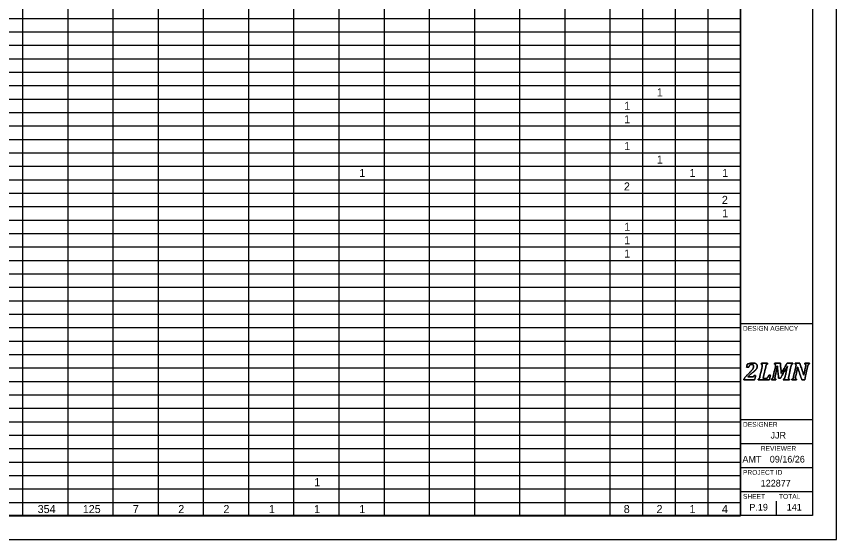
# Model space of a CAD drawing. Extents: x 0 to 34, y 0 to 22.
# Drawn here: x 16.92 to 34, y 0 to 10.9 of the extents above; entities that cross this region are included whole.
import ezdxf

# ---------------------------------------------------------------- set-up
doc = ezdxf.new("R2010")
doc.units = 0
for name, color, linetype in [('SH_Border', 7, 'Continuous'), ('SH_Cut_Line', 7, 'Continuous'), ('SH_Data', 7, 'Continuous'), ('SH_Text', 7, 'Continuous')]:
    doc.layers.add(name, color=color, linetype=linetype)

msp = doc.modelspace()

# ---------------------------------------------------------------- linework, layer by layer
at = {"layer": 'SH_Border'}
for p, q in [((32, 0.5), (32, 21.5)), ((32, 4.5), (33.5, 4.5)), ((32, 2.5), (33.5, 2.5)), ((32, 2), (33.5, 2)), ((32, 1.5), (33.5, 1.5)), ((32, 1), (33.5, 1))]:
    msp.add_line(p, q, dxfattribs=at)
msp.add_lwpolyline([(1.5, 21.5), (33.5, 21.5), (33.5, 0.5), (1.5, 0.5)], close=True, dxfattribs=at)
at = {"layer": 'SH_Cut_Line'}
msp.add_lwpolyline([(0, 0), (34, 0), (34, 22), (0, 22)], close=True, dxfattribs=at)
at = {"layer": 'SH_Data'}
for p, q in [((32.75, 3.5), (32.75, 3.5)), ((32.75, 0.5), (32.75, 0.8)), ((32.375, 0.675), (32.375, 0.675))]:
    msp.add_line(p, q, dxfattribs=at)
for points in [[(32.237, 3.388), (32.246, 3.388), (32.253, 3.389), (32.258, 3.39), (32.263, 3.392), (32.267, 3.394), (32.27, 3.397), (32.273, 3.401), (32.277, 3.408), (32.281, 3.417), (32.281, 3.417), (32.312, 3.417), (32.312, 3.417), (32.312, 3.417), (32.29, 3.326), (32.29, 3.326), (32.29, 3.326), (32.066, 3.326), (32.066, 3.326), (32.066, 3.326), (32.069, 3.343), (32.069, 3.343), (32.078, 3.358), (32.091, 3.375), (32.106, 3.394), (32.122, 3.412), (32.144, 3.435), (32.172, 3.462), (32.197, 3.486), (32.217, 3.506), (32.23, 3.521), (32.243, 3.537), (32.253, 3.551), (32.259, 3.566), (32.266, 3.58), (32.269, 3.595), (32.269, 3.61), (32.269, 3.622), (32.266, 3.632), (32.26, 3.64), (32.253, 3.647), (32.245, 3.65), (32.234, 3.65), (32.22, 3.65), (32.208, 3.646), (32.198, 3.636), (32.188, 3.627), (32.18, 3.613), (32.172, 3.593), (32.172, 3.593), (32.126, 3.593), (32.126, 3.593), (32.126, 3.593), (32.14, 3.654), (32.14, 3.654), (32.166, 3.663), (32.188, 3.669), (32.205, 3.673), (32.223, 3.676), (32.24, 3.678), (32.258, 3.678), (32.278, 3.678), (32.295, 3.675), (32.309, 3.669), (32.322, 3.664), (32.332, 3.656), (32.339, 3.646), (32.345, 3.637), (32.348, 3.626), (32.348, 3.613), (32.348, 3.602), (32.346, 3.591), (32.342, 3.581), (32.339, 3.571), (32.333, 3.56), (32.324, 3.549), (32.315, 3.539), (32.304, 3.526), (32.289, 3.513), (32.275, 3.499), (32.254, 3.482), (32.228, 3.46), (32.216, 3.45), (32.202, 3.438), (32.188, 3.425), (32.174, 3.412), (32.162, 3.4), (32.154, 3.391), (32.154, 3.391), (32.153, 3.388), (32.153, 3.388), (32.153, 3.388), (32.237, 3.388), (32.237, 3.388)], [(32.237, 3.388), (32.237, 3.388), (32.153, 3.388), (32.153, 3.388), (32.153, 3.388), (32.154, 3.391), (32.154, 3.391), (32.162, 3.4), (32.174, 3.412), (32.188, 3.425), (32.202, 3.438), (32.216, 3.45), (32.228, 3.46), (32.254, 3.482), (32.275, 3.499), (32.289, 3.513), (32.304, 3.526), (32.315, 3.539), (32.324, 3.549), (32.333, 3.56), (32.339, 3.571), (32.342, 3.581), (32.346, 3.591), (32.348, 3.602), (32.348, 3.613), (32.348, 3.626), (32.345, 3.637), (32.339, 3.646), (32.332, 3.656), (32.322, 3.664), (32.309, 3.669), (32.295, 3.675), (32.278, 3.678), (32.258, 3.678), (32.24, 3.678), (32.223, 3.676), (32.205, 3.673), (32.188, 3.669), (32.166, 3.663), (32.14, 3.654), (32.14, 3.654), (32.126, 3.593), (32.126, 3.593), (32.126, 3.593), (32.172, 3.593), (32.172, 3.593), (32.18, 3.613), (32.188, 3.627), (32.198, 3.636), (32.208, 3.646), (32.22, 3.65), (32.234, 3.65), (32.245, 3.65), (32.253, 3.647), (32.26, 3.64), (32.266, 3.632), (32.269, 3.622), (32.269, 3.61), (32.269, 3.595), (32.266, 3.58), (32.259, 3.566), (32.253, 3.551), (32.243, 3.537), (32.23, 3.521), (32.217, 3.506), (32.197, 3.486), (32.172, 3.462), (32.144, 3.435), (32.122, 3.412), (32.106, 3.394), (32.091, 3.375), (32.078, 3.358), (32.069, 3.343), (32.069, 3.343), (32.066, 3.326), (32.066, 3.326), (32.066, 3.326), (32.29, 3.326), (32.29, 3.326), (32.29, 3.326), (32.312, 3.417), (32.312, 3.417), (32.312, 3.417), (32.281, 3.417), (32.281, 3.417), (32.277, 3.408), (32.273, 3.401), (32.27, 3.397), (32.267, 3.394), (32.263, 3.392), (32.258, 3.39), (32.253, 3.389), (32.246, 3.388), (32.237, 3.388)], [(32.518, 3.356), (32.527, 3.356), (32.533, 3.357), (32.538, 3.358), (32.542, 3.36), (32.546, 3.362), (32.55, 3.365), (32.554, 3.368), (32.558, 3.372), (32.562, 3.377), (32.567, 3.382), (32.571, 3.388), (32.576, 3.397), (32.58, 3.405), (32.585, 3.415), (32.589, 3.427), (32.589, 3.427), (32.624, 3.427), (32.624, 3.427), (32.624, 3.427), (32.598, 3.326), (32.598, 3.326), (32.598, 3.326), (32.365, 3.326), (32.365, 3.326), (32.365, 3.326), (32.369, 3.343), (32.369, 3.343), (32.376, 3.345), (32.381, 3.348), (32.385, 3.351), (32.389, 3.355), (32.392, 3.36), (32.395, 3.366), (32.398, 3.373), (32.4, 3.382), (32.403, 3.395), (32.403, 3.395), (32.449, 3.605), (32.449, 3.605), (32.452, 3.615), (32.453, 3.625), (32.453, 3.635), (32.453, 3.642), (32.451, 3.647), (32.448, 3.651), (32.444, 3.654), (32.439, 3.656), (32.432, 3.657), (32.432, 3.657), (32.435, 3.674), (32.435, 3.674), (32.435, 3.674), (32.563, 3.674), (32.563, 3.674), (32.563, 3.674), (32.559, 3.657), (32.559, 3.657), (32.552, 3.655), (32.547, 3.652), (32.543, 3.649), (32.539, 3.645), (32.536, 3.64), (32.533, 3.634), (32.531, 3.627), (32.528, 3.618), (32.525, 3.605), (32.525, 3.605), (32.47, 3.356), (32.47, 3.356), (32.47, 3.356), (32.518, 3.356), (32.518, 3.356)], [(32.518, 3.356), (32.518, 3.356), (32.47, 3.356), (32.47, 3.356), (32.47, 3.356), (32.525, 3.605), (32.525, 3.605), (32.528, 3.618), (32.531, 3.627), (32.533, 3.634), (32.536, 3.64), (32.539, 3.645), (32.543, 3.649), (32.547, 3.652), (32.552, 3.655), (32.559, 3.657), (32.559, 3.657), (32.563, 3.674), (32.563, 3.674), (32.563, 3.674), (32.435, 3.674), (32.435, 3.674), (32.435, 3.674), (32.432, 3.657), (32.432, 3.657), (32.439, 3.656), (32.444, 3.654), (32.448, 3.651), (32.451, 3.647), (32.453, 3.642), (32.453, 3.635), (32.453, 3.625), (32.452, 3.615), (32.449, 3.605), (32.449, 3.605), (32.403, 3.395), (32.403, 3.395), (32.4, 3.382), (32.398, 3.373), (32.395, 3.366), (32.392, 3.36), (32.389, 3.355), (32.385, 3.351), (32.381, 3.348), (32.376, 3.345), (32.369, 3.343), (32.369, 3.343), (32.365, 3.326), (32.365, 3.326), (32.365, 3.326), (32.598, 3.326), (32.598, 3.326), (32.598, 3.326), (32.624, 3.427), (32.624, 3.427), (32.624, 3.427), (32.589, 3.427), (32.589, 3.427), (32.585, 3.415), (32.58, 3.405), (32.576, 3.397), (32.571, 3.388), (32.567, 3.382), (32.562, 3.377), (32.558, 3.372), (32.554, 3.368), (32.55, 3.365), (32.546, 3.362), (32.542, 3.36), (32.538, 3.358), (32.533, 3.357), (32.527, 3.356), (32.518, 3.356)], [(32.829, 3.674), (32.829, 3.674), (32.849, 3.461), (32.849, 3.461), (32.849, 3.461), (32.969, 3.674), (32.969, 3.674), (32.969, 3.674), (33.087, 3.674), (33.087, 3.674), (33.087, 3.674), (33.084, 3.657), (33.084, 3.657), (33.077, 3.655), (33.071, 3.652), (33.067, 3.649), (33.064, 3.645), (33.06, 3.64), (33.058, 3.634), (33.055, 3.627), (33.052, 3.618), (33.05, 3.605), (33.05, 3.605), (33.003, 3.395), (33.003, 3.395), (33.002, 3.39), (33.002, 3.387), (33.001, 3.384), (33.001, 3.382), (33.001, 3.379), (33, 3.376), (33, 3.373), (33, 3.369), (33, 3.365), (33, 3.358), (33.002, 3.353), (33.005, 3.349), (33.008, 3.346), (33.014, 3.344), (33.021, 3.343), (33.021, 3.343), (33.018, 3.326), (33.018, 3.326), (33.018, 3.326), (32.89, 3.326), (32.89, 3.326), (32.89, 3.326), (32.893, 3.343), (32.893, 3.343), (32.9, 3.345), (32.906, 3.348), (32.91, 3.351), (32.914, 3.355), (32.917, 3.36), (32.919, 3.366), (32.922, 3.373), (32.925, 3.382), (32.928, 3.395), (32.928, 3.395), (32.951, 3.502), (32.951, 3.502), (32.954, 3.513), (32.957, 3.529), (32.962, 3.548), (32.967, 3.568), (32.972, 3.588), (32.978, 3.609), (32.978, 3.609), (32.973, 3.609), (32.973, 3.609), (32.965, 3.594), (32.957, 3.579), (32.948, 3.563), (32.948, 3.563), (32.833, 3.364), (32.833, 3.364), (32.833, 3.364), (32.792, 3.364), (32.792, 3.364), (32.792, 3.364), (32.775, 3.518), (32.775, 3.518), (32.773, 3.537), (32.772, 3.554), (32.77, 3.569), (32.769, 3.583), (32.768, 3.597), (32.768, 3.611), (32.768, 3.611), (32.764, 3.611), (32.764, 3.611), (32.761, 3.596), (32.758, 3.578), (32.755, 3.558), (32.751, 3.538), (32.747, 3.521), (32.744, 3.507), (32.744, 3.507), (32.72, 3.395), (32.72, 3.395), (32.719, 3.39), (32.718, 3.387), (32.718, 3.384), (32.717, 3.382), (32.717, 3.379), (32.717, 3.376), (32.717, 3.373), (32.716, 3.369), (32.716, 3.365), (32.716, 3.358), (32.718, 3.353), (32.721, 3.349), (32.725, 3.346), (32.73, 3.344), (32.738, 3.343), (32.738, 3.343), (32.734, 3.326), (32.734, 3.326), (32.734, 3.326), (32.641, 3.326), (32.641, 3.326), (32.641, 3.326), (32.644, 3.343), (32.644, 3.343), (32.651, 3.345), (32.657, 3.348), (32.661, 3.351), (32.665, 3.355), (32.668, 3.36), (32.67, 3.366), (32.673, 3.373), (32.676, 3.382), (32.679, 3.395), (32.679, 3.395), (32.725, 3.605), (32.725, 3.605), (32.727, 3.615), (32.728, 3.625), (32.728, 3.635), (32.728, 3.642), (32.727, 3.647), (32.723, 3.651), (32.72, 3.654), (32.715, 3.656), (32.707, 3.657), (32.707, 3.657), (32.711, 3.674), (32.711, 3.674), (32.711, 3.674), (32.829, 3.674), (32.829, 3.674)], [(32.829, 3.674), (32.829, 3.674), (32.711, 3.674), (32.711, 3.674), (32.711, 3.674), (32.707, 3.657), (32.707, 3.657), (32.715, 3.656), (32.72, 3.654), (32.723, 3.651), (32.727, 3.647), (32.728, 3.642), (32.728, 3.635), (32.728, 3.625), (32.727, 3.615), (32.725, 3.605), (32.725, 3.605), (32.679, 3.395), (32.679, 3.395), (32.676, 3.382), (32.673, 3.373), (32.67, 3.366), (32.668, 3.36), (32.665, 3.355), (32.661, 3.351), (32.657, 3.348), (32.651, 3.345), (32.644, 3.343), (32.644, 3.343), (32.641, 3.326), (32.641, 3.326), (32.641, 3.326), (32.734, 3.326), (32.734, 3.326), (32.734, 3.326), (32.738, 3.343), (32.738, 3.343), (32.73, 3.344), (32.725, 3.346), (32.721, 3.349), (32.718, 3.353), (32.716, 3.358), (32.716, 3.365), (32.716, 3.369), (32.717, 3.373), (32.717, 3.376), (32.717, 3.379), (32.717, 3.382), (32.718, 3.384), (32.718, 3.387), (32.719, 3.39), (32.72, 3.395), (32.72, 3.395), (32.744, 3.507), (32.744, 3.507), (32.747, 3.521), (32.751, 3.538), (32.755, 3.558), (32.758, 3.578), (32.761, 3.596), (32.764, 3.611), (32.764, 3.611), (32.768, 3.611), (32.768, 3.611), (32.768, 3.597), (32.769, 3.583), (32.77, 3.569), (32.772, 3.554), (32.773, 3.537), (32.775, 3.518), (32.775, 3.518), (32.792, 3.364), (32.792, 3.364), (32.792, 3.364), (32.833, 3.364), (32.833, 3.364), (32.833, 3.364), (32.948, 3.563), (32.948, 3.563), (32.957, 3.579), (32.965, 3.594), (32.973, 3.609), (32.973, 3.609), (32.978, 3.609), (32.978, 3.609), (32.972, 3.588), (32.967, 3.568), (32.962, 3.548), (32.957, 3.529), (32.954, 3.513), (32.951, 3.502), (32.951, 3.502), (32.928, 3.395), (32.928, 3.395), (32.925, 3.382), (32.922, 3.373), (32.919, 3.366), (32.917, 3.36), (32.914, 3.355), (32.91, 3.351), (32.906, 3.348), (32.9, 3.345), (32.893, 3.343), (32.893, 3.343), (32.89, 3.326), (32.89, 3.326), (32.89, 3.326), (33.018, 3.326), (33.018, 3.326), (33.018, 3.326), (33.021, 3.343), (33.021, 3.343), (33.014, 3.344), (33.008, 3.346), (33.005, 3.349), (33.002, 3.353), (33, 3.358), (33, 3.365), (33, 3.369), (33, 3.373), (33, 3.376), (33.001, 3.379), (33.001, 3.382), (33.001, 3.384), (33.002, 3.387), (33.002, 3.39), (33.003, 3.395), (33.003, 3.395), (33.05, 3.605), (33.05, 3.605), (33.052, 3.618), (33.055, 3.627), (33.058, 3.634), (33.06, 3.64), (33.064, 3.645), (33.067, 3.649), (33.071, 3.652), (33.077, 3.655), (33.084, 3.657), (33.084, 3.657), (33.087, 3.674), (33.087, 3.674), (33.087, 3.674), (32.969, 3.674), (32.969, 3.674), (32.969, 3.674), (32.849, 3.461), (32.849, 3.461), (32.849, 3.461), (32.829, 3.674), (32.829, 3.674)], [(33.137, 3.674), (33.137, 3.674), (33.234, 3.674), (33.234, 3.674), (33.234, 3.674), (33.283, 3.53), (33.283, 3.53), (33.296, 3.49), (33.307, 3.456), (33.315, 3.426), (33.315, 3.426), (33.318, 3.426), (33.318, 3.426), (33.323, 3.455), (33.329, 3.488), (33.337, 3.523), (33.337, 3.523), (33.355, 3.605), (33.355, 3.605), (33.357, 3.615), (33.358, 3.625), (33.358, 3.635), (33.358, 3.642), (33.357, 3.647), (33.353, 3.651), (33.35, 3.654), (33.345, 3.656), (33.337, 3.657), (33.337, 3.657), (33.341, 3.674), (33.341, 3.674), (33.341, 3.674), (33.434, 3.674), (33.434, 3.674), (33.434, 3.674), (33.431, 3.657), (33.431, 3.657), (33.424, 3.655), (33.418, 3.652), (33.414, 3.649), (33.41, 3.645), (33.407, 3.64), (33.405, 3.634), (33.402, 3.627), (33.399, 3.618), (33.396, 3.605), (33.396, 3.605), (33.335, 3.326), (33.335, 3.326), (33.335, 3.326), (33.277, 3.326), (33.277, 3.326), (33.277, 3.326), (33.216, 3.504), (33.216, 3.504), (33.211, 3.518), (33.207, 3.531), (33.204, 3.543), (33.2, 3.556), (33.195, 3.571), (33.19, 3.59), (33.19, 3.59), (33.186, 3.59), (33.186, 3.59), (33.185, 3.579), (33.182, 3.563), (33.179, 3.543), (33.175, 3.523), (33.17, 3.501), (33.165, 3.478), (33.165, 3.478), (33.147, 3.395), (33.147, 3.395), (33.146, 3.39), (33.145, 3.387), (33.145, 3.384), (33.144, 3.382), (33.144, 3.379), (33.144, 3.376), (33.143, 3.373), (33.143, 3.369), (33.143, 3.365), (33.143, 3.358), (33.145, 3.353), (33.148, 3.349), (33.152, 3.346), (33.157, 3.344), (33.164, 3.343), (33.164, 3.343), (33.161, 3.326), (33.161, 3.326), (33.161, 3.326), (33.067, 3.326), (33.067, 3.326), (33.067, 3.326), (33.071, 3.343), (33.071, 3.343), (33.078, 3.345), (33.083, 3.348), (33.087, 3.351), (33.091, 3.355), (33.094, 3.36), (33.097, 3.366), (33.1, 3.373), (33.102, 3.382), (33.105, 3.395), (33.105, 3.395), (33.151, 3.605), (33.151, 3.605), (33.154, 3.615), (33.155, 3.625), (33.155, 3.635), (33.155, 3.642), (33.153, 3.647), (33.15, 3.651), (33.146, 3.654), (33.141, 3.656), (33.134, 3.657), (33.134, 3.657), (33.137, 3.674), (33.137, 3.674)], [(33.137, 3.674), (33.137, 3.674), (33.134, 3.657), (33.134, 3.657), (33.141, 3.656), (33.146, 3.654), (33.15, 3.651), (33.153, 3.647), (33.155, 3.642), (33.155, 3.635), (33.155, 3.625), (33.154, 3.615), (33.151, 3.605), (33.151, 3.605), (33.105, 3.395), (33.105, 3.395), (33.102, 3.382), (33.1, 3.373), (33.097, 3.366), (33.094, 3.36), (33.091, 3.355), (33.087, 3.351), (33.083, 3.348), (33.078, 3.345), (33.071, 3.343), (33.071, 3.343), (33.067, 3.326), (33.067, 3.326), (33.067, 3.326), (33.161, 3.326), (33.161, 3.326), (33.161, 3.326), (33.164, 3.343), (33.164, 3.343), (33.157, 3.344), (33.152, 3.346), (33.148, 3.349), (33.145, 3.353), (33.143, 3.358), (33.143, 3.365), (33.143, 3.369), (33.143, 3.373), (33.144, 3.376), (33.144, 3.379), (33.144, 3.382), (33.145, 3.384), (33.145, 3.387), (33.146, 3.39), (33.147, 3.395), (33.147, 3.395), (33.165, 3.478), (33.165, 3.478), (33.17, 3.501), (33.175, 3.523), (33.179, 3.543), (33.182, 3.563), (33.185, 3.579), (33.186, 3.59), (33.186, 3.59), (33.19, 3.59), (33.19, 3.59), (33.195, 3.571), (33.2, 3.556), (33.204, 3.543), (33.207, 3.531), (33.211, 3.518), (33.216, 3.504), (33.216, 3.504), (33.277, 3.326), (33.277, 3.326), (33.277, 3.326), (33.335, 3.326), (33.335, 3.326), (33.335, 3.326), (33.396, 3.605), (33.396, 3.605), (33.399, 3.618), (33.402, 3.627), (33.405, 3.634), (33.407, 3.64), (33.41, 3.645), (33.414, 3.649), (33.418, 3.652), (33.424, 3.655), (33.431, 3.657), (33.431, 3.657), (33.434, 3.674), (33.434, 3.674), (33.434, 3.674), (33.341, 3.674), (33.341, 3.674), (33.341, 3.674), (33.337, 3.657), (33.337, 3.657), (33.345, 3.656), (33.35, 3.654), (33.353, 3.651), (33.357, 3.647), (33.358, 3.642), (33.358, 3.635), (33.358, 3.625), (33.357, 3.615), (33.355, 3.605), (33.355, 3.605), (33.337, 3.523), (33.337, 3.523), (33.329, 3.488), (33.323, 3.455), (33.318, 3.426), (33.318, 3.426), (33.315, 3.426), (33.315, 3.426), (33.307, 3.456), (33.296, 3.49), (33.283, 3.53), (33.283, 3.53), (33.234, 3.674), (33.234, 3.674), (33.234, 3.674), (33.137, 3.674), (33.137, 3.674)]]:
    msp.add_open_spline(points, degree=3, dxfattribs=at)
at = {"layer": 'SH_Text'}
for p, q in [((17.047, 21.5), (17.047, 0.496)), ((17.988, 21.5), (17.988, 0.496)), ((18.929, 21.5), (18.929, 0.496)), ((19.869, 21.5), (19.869, 0.496)), ((20.81, 21.5), (20.81, 0.496)), ((21.751, 21.5), (21.751, 0.496)), ((22.692, 21.5), (22.692, 0.496)), ((23.633, 21.5), (23.633, 0.496)), ((24.574, 21.5), (24.574, 0.496)), ((25.515, 21.5), (25.515, 0.496)), ((26.456, 21.5), (26.456, 0.496)), ((27.397, 21.5), (27.397, 0.496)), ((28.338, 21.5), (28.338, 0.496)), ((29.279, 21.5), (29.279, 0.496)), ((32, 21.5), (32, 0.496)), ((29.959, 20.94), (29.959, 0.496)), ((30.639, 20.94), (30.639, 0.496)), ((31.32, 20.94), (31.32, 0.496)), ((1.5, 10.858), (32, 10.858)), ((1.5, 10.578), (32, 10.578)), ((1.5, 10.298), (32, 10.298)), ((1.5, 10.018), (32, 10.018)), ((1.5, 9.738), (32, 9.738)), ((1.5, 9.458), (32, 9.458)), ((1.5, 9.178), (32, 9.178)), ((1.5, 8.898), (32, 8.898)), ((1.5, 8.618), (32, 8.618)), ((1.5, 8.338), (32, 8.338)), ((1.5, 8.058), (32, 8.058)), ((1.5, 7.777), (32, 7.777)), ((1.5, 7.497), (32, 7.497)), ((1.5, 7.217), (32, 7.217)), ((1.5, 6.937), (32, 6.937)), ((1.5, 6.657), (32, 6.657)), ((1.5, 6.377), (32, 6.377)), ((1.5, 6.097), (32, 6.097)), ((1.5, 5.817), (32, 5.817)), ((1.5, 5.537), (32, 5.537)), ((1.5, 5.257), (32, 5.257)), ((1.5, 4.977), (32, 4.977)), ((1.5, 4.697), (32, 4.697)), ((1.5, 4.417), (32, 4.417)), ((1.5, 4.137), (32, 4.137)), ((1.5, 3.857), (32, 3.857)), ((1.5, 3.577), (32, 3.577)), ((1.5, 3.297), (32, 3.297)), ((1.5, 3.017), (32, 3.017)), ((1.5, 2.737), (32, 2.737)), ((1.5, 2.456), (32, 2.456)), ((1.5, 2.176), (32, 2.176)), ((1.5, 1.896), (32, 1.896)), ((1.5, 1.616), (32, 1.616)), ((1.5, 1.336), (32, 1.336)), ((1.5, 1.056), (32, 1.056)), ((1.5, 0.776), (32, 0.776)), ((1.5, 0.496), (32, 0.496))]:
    msp.add_line(p, q, dxfattribs=at)

# ---------------------------------------------------------------- texts
at = {"layer": 'SH_Data'}
for s, height, p in [('DESIGN AGENCY', 0.1, (32.05, 4.35)), ('DESIGNER', 0.1, (32.05, 2.35)), ('JJR', 0.14, (32.624, 2.105)), ('REVIEWER', 0.1, (32.422, 1.85)), ('AMT', 0.14, (32.039, 1.605)), ('09/16/26', 0.14, (32.609, 1.605)), ('PROJECT ID', 0.1, (32.05, 1.35)), ('122877', 0.14, (32.42, 1.105)), ('SHEET', 0.1, (32.05, 0.85)), ('TOTAL', 0.1, (32.8, 0.85)), ('P.19', 0.14, (32.184, 0.605)), ('141', 0.14, (32.963, 0.605))]:
    msp.add_text(s, height=height, dxfattribs=at).set_placement(p)
at = {"layer": 'SH_Text'}
for s, height, p in [('1', 0.167, (30.256, 9.234)), ('1', 0.167, (29.576, 8.954)), ('1', 0.167, (29.576, 8.674)), ('1', 0.167, (29.576, 8.114)), ('1', 0.167, (30.256, 7.834)), ('1', 0.167, (24.06, 7.554)), ('1', 0.167, (30.936, 7.554)), ('1', 0.167, (31.617, 7.554)), ('2', 0.167, (29.57, 7.274)), ('2', 0.167, (31.611, 6.994)), ('1', 0.167, (31.617, 6.714)), ('1', 0.167, (29.576, 6.434)), ('1', 0.167, (29.576, 6.154)), ('1', 0.167, (29.576, 5.874)), ('1', 0.167, (23.12, 1.113)), ('354', 0.1667, (17.361, 0.553)), ('125', 0.1667, (18.301, 0.553)), ('7', 0.167, (19.343, 0.553)), ('2', 0.167, (20.289, 0.553)), ('2', 0.167, (21.23, 0.553)), ('1', 0.167, (22.177, 0.553)), ('1', 0.167, (23.118, 0.553)), ('1', 0.167, (24.059, 0.553)), ('8', 0.167, (29.567, 0.553)), ('2', 0.167, (30.25, 0.553)), ('1', 0.167, (30.936, 0.553)), ('4', 0.167, (31.611, 0.553))]:
    msp.add_text(s, height=height, dxfattribs=at).set_placement(p)

doc.saveas('drawing.dxf')
